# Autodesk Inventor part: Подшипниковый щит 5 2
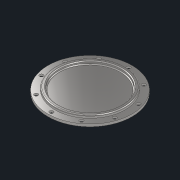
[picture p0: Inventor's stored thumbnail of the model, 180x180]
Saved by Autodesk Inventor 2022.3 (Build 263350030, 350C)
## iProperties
Created: 2022-08
Part Number: Подшипниковый щит 5 2
Material: Сталь 40ХНМА
Document SubType Name: Modeling
Designer: Карташов
Density: 7.85 g/cm^3
Appearance: С умеренной полировкой
Author: Карташов
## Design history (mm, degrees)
sketch "Эскиз1"
  geometry: L1 (0, 0)-(0, 34.001); L2 (50, -5)-(90, -5); L3 (90, -5)-(90, 0); L4 (90, 0)-(75, 0); L5 (75, 0)-(75, 4); L6 (73, 6)-(69, 6); L7 (67, 4)-(67, 2); L8 (65, 0)-(0, 0); L9 (50, -5)-(48, -7); L10 (48, -7)-(0, -7); L11 (0, -7)-(0, 0); A1 r 2 centre (65, 2) between (65, 0) and (67, 2); A2 r 2 centre (73, 4) between (75, 4) and (73, 6); A3 r 2 centre (69, 4) between (69, 6) and (67, 4); 4 further points
  constraints: 22 end point, 6 point on circle, 6 tangent, 5 horizontal, 4 point on line, 3 centre point, 3 vertical, 2 midpoint, 2 perpendicular
  dimensions: "d0" = 150 diameter of L5 point (0, 17); "d1" = 180 diameter of L3 L1; "d4" = 5 distance of L2.end L3.end; "d5" = 6 distance between parallel lines of L8 L6; "d6" = 8 distance of point (75, 6) point (67, 6); "d7" = 2 radius of A1; "d21" = 2 horizontal distance of L2.start L9.end; "d22" = 2 horizontal distance of L2.start L9.end; "d23" = 100 diameter of L2.start L1; "d24" = 2 radius of A2; "d25" = 2 radius of A3 (derived); "d26" = 13 distance from line of point (71, 6) L10
revolve "Вращение1" sketch "Эскиз1" stored, may be unused: angle "d9" = 90 deg
sketch "Эскиз2"
  geometry: C1 r 75 at (0, 0) reference; C2 r 90 at (0, 0) reference; 2 further points
  constraints: 1 vertical alignment
  dimensions: "d10" = 82.5 distance of point (0, 0) point (0, -82.5)
  node "Спроецированная петля1"
sketch "Эскиз3"
  geometry: 2 further points
hole "Отверстие1" sketch "Эскиз3" at (0, 82.5) diameter "d11" = 8; stored, may be unused: countersink angle "d15" = 90 deg, drill point angle "d17" = 0 deg; dims "d12" = 6, "d13" = 13, "d14" = 1, "d16" = 22.5
pattern_circular "Круговой массив1" dims angle "d19" = 360 deg
node "Твердое тело1"
